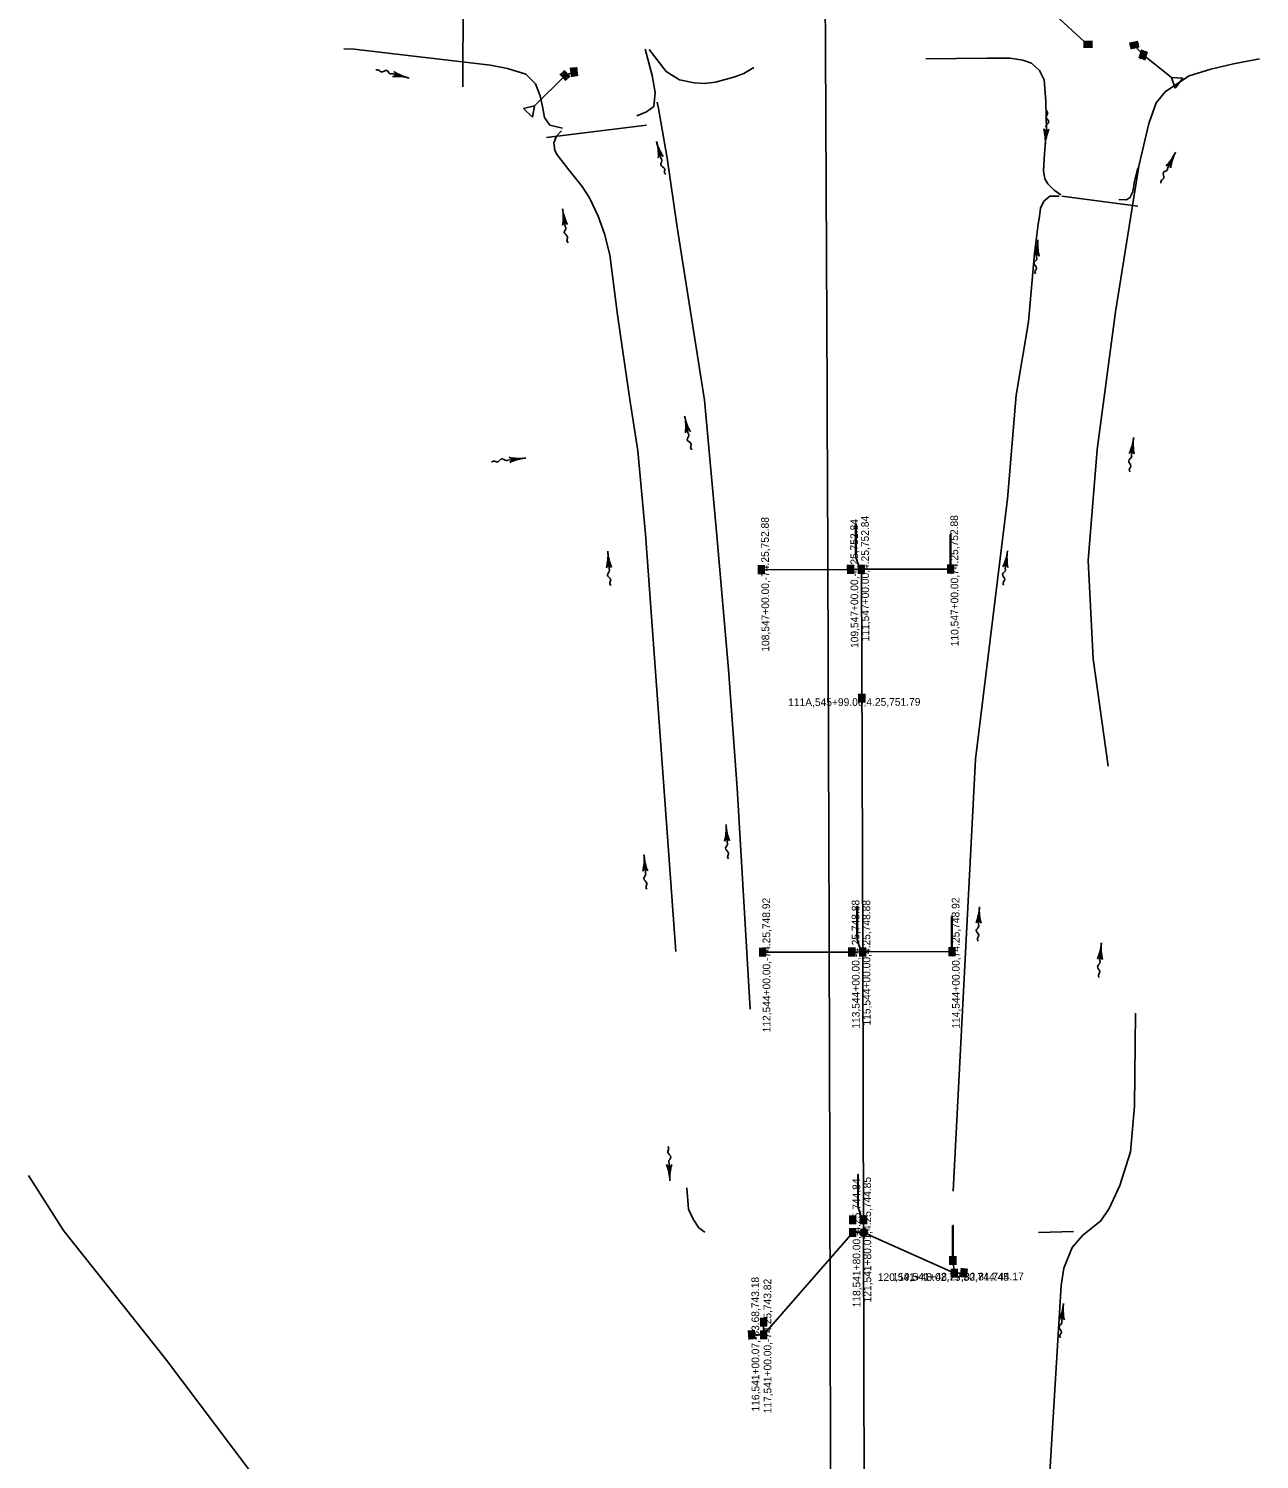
# Model space of a CAD drawing. Extents: x 593481 to 595859, y 101157 to 225994.
# Drawn here: x 593709 to 594675, y 153277 to 154399 of the extents above; entities that cross this region are included whole.
import ezdxf

# ---------------------------------------------------------------- set-up
doc = ezdxf.new("R2010")
doc.units = 0
for name, color, linetype in [('Default', 7, 'Continuous'), ('E_DTM_SpotElev', 7, 'Continuous'), ('E_PROF_GridMin', 7, 'Continuous'), ('Level 6', 7, 'Continuous'), ('P_DRN_SS_UG', 7, 'Continuous'), ('P_MAP_ContoursInter', 7, 'Continuous'), ('P_RDWY_C_and_G_H', 7, 'Continuous')]:
    doc.layers.add(name, color=color, linetype=linetype)

msp = doc.modelspace()

# ---------------------------------------------------------------- linework, layer by layer
at = {"layer": 'Default'}
msp.add_line((594334.5, 154382.7), (594308.8, 159385.6), dxfattribs=at)
msp.add_arc((250574.3, 152618.3), 343764.7, 0.103013, 0.29409, dxfattribs=at)
at = {"layer": 'E_DTM_SpotElev'}
for p, q in [((594008, 154360.4), (593994.3, 154363.9)), ((594506.8, 154307.6), (594507.7, 154321.7)), ((594201.9, 154310.7), (594205.6, 154297.1)), ((594608.9, 154302.3), (594602.8, 154289.6)), ((594128.3, 154257.9), (594130.4, 154244)), ((594501.1, 154233.7), (594499.9, 154219.7)), ((594224.1, 154095.3), (594226.8, 154081.5)), ((594576.1, 154078.6), (594574.4, 154064.6)), ((594099.4, 154062.5), (594085.3, 154060.9)), ((594163.8, 153989.4), (594164.8, 153975.3)), ((594477.1, 153989.6), (594475.4, 153975.6)), ((594256.5, 153775.1), (594257.3, 153761)), ((594192.2, 153751.4), (594193.2, 153737.3)), ((594455.2, 153710.7), (594454.5, 153696.6)), ((594550.8, 153682.3), (594549.7, 153668.2)), ((594212.5, 153495.8), (594211.8, 153509.9)), ((594521, 153399.7), (594519.7, 153385.7))]:
    msp.add_line(p, q, dxfattribs=at)
for points in [[(593995.1, 154361.6), (593998.7, 154362.7), (593996, 154365.5)], [(594505.6, 154320.5), (594507.4, 154317.2), (594509.6, 154320.3)], [(594207.2, 154298.9), (594204.4, 154301.5), (594203.3, 154297.9)], [(594605.2, 154289.9), (594604.8, 154293.7), (594601.6, 154291.7)], [(594132.2, 154245.6), (594129.7, 154248.4), (594128.2, 154245)], [(594502, 154220.8), (594500.3, 154224.2), (594498, 154221.1)], [(594228.5, 154083.2), (594225.9, 154085.9), (594224.6, 154082.4)], [(594086.9, 154059.1), (594089.8, 154061.4), (594086.4, 154063.1)], [(594576.5, 154065.7), (594575, 154069.1), (594572.6, 154066.1)], [(594166.7, 153976.8), (594164.4, 153979.8), (594162.7, 153976.5)], [(594477.6, 153976.7), (594476, 153980.1), (594473.6, 153977.2)], [(594259.2, 153762.5), (594257.1, 153765.6), (594255.2, 153762.2)], [(594195.1, 153738.8), (594192.8, 153741.8), (594191.1, 153738.5)], [(594456.5, 153697.9), (594454.7, 153701.2), (594452.6, 153698.1)], [(594551.8, 153669.3), (594550, 153672.7), (594547.8, 153669.7)], [(594209.9, 153508.5), (594212, 153505.4), (594213.9, 153508.7)], [(594521.8, 153386.8), (594520.1, 153390.2), (594517.8, 153387.2)]]:
    msp.add_lwpolyline(points, dxfattribs=at)
for centre, start, end in [((594018.2, 154401.1), 238.1531, 255.9155), ((593997.7, 154319.7), 75.9155, 93.6778), ((594464.9, 154310.2), 356.5125, 14.2748), ((594548.7, 154305.1), 158.7502, 176.5125), ((594242.4, 154321.7), 195.1541, 212.9164), ((594161.4, 154299.8), 357.3917, 15.1541), ((594571.2, 154320.6), 316.3732, 334.1356), ((594646.7, 154284), 154.1356, 171.8979), ((594086.8, 154251.8), 350.6256, 8.3879), ((594169.8, 154264), 188.3879, 206.1502), ((594459.2, 154237.1), 337.5935, 355.3558), ((594542.9, 154230.3), 175.3558, 193.1182), ((594265.2, 154103.5), 191.2545, 209.0168), ((594182.9, 154087.1), 353.4922, 11.2545), ((594534.5, 154083.7), 335.2209, 352.9833), ((594617.8, 154073.5), 172.9833, 190.7456), ((594094.6, 154104.2), 258.7469, 276.5092), ((594104.1, 154020.8), 96.5092, 114.2715), ((594121.9, 153986.4), 346.3551, 4.1174), ((594205.6, 153992.4), 184.1174, 201.8798), ((594435.5, 153994.8), 335.1954, 352.9578), ((594518.8, 153984.5), 172.9578, 190.7201), ((594214.6, 153772.7), 345.5959, 3.3582), ((594298.4, 153777.6), 183.3582, 201.1205), ((594150.3, 153748.4), 346.3551, 4.1174), ((594234, 153754.4), 184.1174, 201.8798), ((594413.3, 153712.9), 339.294, 357.0563), ((594497.1, 153708.6), 177.0563, 194.8186), ((594509, 153685.6), 337.6021, 355.3644), ((594592.6, 153678.9), 175.3644, 193.1267), ((594170.5, 153493.9), 2.5881, 20.3505), ((594254.4, 153497.7), 164.8258, 182.5881), ((594479.3, 153403.8), 336.6726, 354.435), ((594562.8, 153395.7), 174.435, 192.1973)]:
    msp.add_arc(centre, 42, start, end, dxfattribs=at)
for points in [[(593994.3, 154363.9), (593993.4, 154363.7), (593990.4, 154366.4), (593986, 154365.3), (593983.5, 154366.9), (593981.7, 154366.7)], [(594507.7, 154321.7), (594507.4, 154322.5), (594509.5, 154326), (594507.5, 154330.1), (594508.7, 154332.8), (594508.1, 154334.6)], [(594205.6, 154297.1), (594206.1, 154296.4), (594205.2, 154292.4), (594208.4, 154289.2), (594208.2, 154286.3), (594209.2, 154284.8)], [(594602.8, 154289.6), (594602.7, 154288.8), (594599.5, 154286.4), (594599.7, 154281.9), (594597.6, 154279.7), (594597.5, 154277.9)], [(594130.4, 154244), (594130.8, 154243.2), (594129.5, 154239.4), (594132.2, 154235.8), (594131.7, 154232.9), (594132.6, 154231.3)], [(594499.9, 154219.7), (594500.2, 154218.8), (594498, 154215.4), (594499.9, 154211.3), (594498.7, 154208.6), (594499.2, 154206.8)], [(594226.8, 154081.5), (594227.3, 154080.8), (594226.1, 154076.9), (594229.1, 154073.4), (594228.7, 154070.5), (594229.6, 154068.9)], [(594085.3, 154060.9), (594084.6, 154060.5), (594080.8, 154062), (594077.1, 154059.4), (594074.2, 154060), (594072.6, 154059.2)], [(594574.4, 154064.6), (594574.6, 154063.8), (594572.3, 154060.4), (594574, 154056.2), (594572.7, 154053.6), (594573.1, 154051.8)], [(594164.8, 153975.3), (594165.1, 153974.5), (594163.5, 153970.8), (594166, 153967), (594165.3, 153964.2), (594166, 153962.5)], [(594475.4, 153975.6), (594475.6, 153974.8), (594473.3, 153971.4), (594475, 153967.3), (594473.7, 153964.6), (594474.1, 153962.8)], [(594257.3, 153761), (594257.7, 153760.3), (594256, 153756.6), (594258.4, 153752.8), (594257.7, 153749.9), (594258.4, 153748.2)], [(594193.2, 153737.3), (594193.5, 153736.5), (594191.9, 153732.8), (594194.4, 153729.1), (594193.7, 153726.2), (594194.4, 153724.5)], [(594454.5, 153696.6), (594454.8, 153695.8), (594452.7, 153692.3), (594454.7, 153688.3), (594453.6, 153685.5), (594454.1, 153683.8)], [(594549.7, 153668.2), (594549.9, 153667.4), (594547.8, 153663.9), (594549.6, 153659.8), (594548.5, 153657.1), (594548.9, 153655.3)], [(594211.8, 153509.9), (594211.5, 153510.7), (594213.2, 153514.4), (594210.8, 153518.2), (594211.6, 153521.1), (594210.9, 153522.8)], [(594519.7, 153385.7), (594519.9, 153384.8), (594517.7, 153381.4), (594519.5, 153377.3), (594518.3, 153374.6), (594518.7, 153372.8)]]:
    msp.add_spline(points, degree=3, dxfattribs=at)
at = {"layer": 'E_PROF_GridMin'}
for p, q in [((594540.5, 154386.1), (594491.5, 154431.2)), ((594576.6, 154386.3), (594583.6, 154378.5)), ((594583.6, 154378.5), (594605.8, 154360.9)), ((594130.2, 154362.4), (594106.2, 154338.6)), ((594137.3, 154365.2), (594130.2, 154362.4)), ((594284.1, 153974.9), (594354.1, 153975.2)), ((594354.1, 153975.2), (594362.6, 153975.3)), ((594432.6, 153975.5), (594362.6, 153975.3)), ((594362.6, 153975.3), (594363.7, 153675.3)), ((594432.6, 153976.5), (594432.6, 153978.5)), ((594433.6, 153676.5), (594433.6, 153679)), ((594285.2, 153675), (594355.2, 153675.2)), ((594355.2, 153675.2), (594363.7, 153675.3)), ((594433.7, 153675.5), (594363.7, 153675.3)), ((594363.7, 153675.3), (594364.3, 153455.3)), ((594285.9, 153375.1), (594355.8, 153455.2)), ((594355.8, 153455.2), (594364.3, 153455.3)), ((594435.6, 153423.4), (594364.3, 153455.3)), ((594364.3, 153455.3), (594364.8, 153184.2)), ((594529, 153456), (594501.6, 153455.4)), ((594434.3, 153434.4), (594434.3, 153436.9)), ((594435.6, 153423.4), (594434.3, 153433.4)), ((594276.5, 153375.1), (594285.9, 153375.1)), ((594285.9, 153375.1), (594285.9, 153385.1))]:
    msp.add_line(p, q, dxfattribs=at)
for points in [[(594128.3, 154321.1), (594118.4, 154323.4), (594114.1, 154329.6), (594112.5, 154338.2), (594110.8, 154346.4), (594107, 154355.8), (594099.4, 154363.4), (594085.1, 154367.9), (594071.8, 154370.5), (593964.7, 154383.1), (593956.8, 154383.2)], [(594193.1, 154383.1), (594198.4, 154362.4), (594201, 154349.1), (594199.9, 154338.2), (594194, 154334), (594186.5, 154330.9)], [(594196.2, 154382.7), (594209.6, 154365.5), (594220, 154358.9), (594231.4, 154356.6), (594239.5, 154356.1), (594248.2, 154357.3), (594263.3, 154361.5), (594270.5, 154363.9), (594278.3, 154368.7)], [(594519, 154268.8), (594513.7, 154272.6), (594508.9, 154277.5), (594506.6, 154281.5), (594505.5, 154288), (594506.3, 154300.9), (594507.7, 154319.7), (594507.3, 154342), (594506, 154359), (594502.3, 154366.3), (594495.9, 154372.1), (594489.3, 154374.5), (594479.3, 154376), (594461.3, 154376), (594413.1, 154375.6)], [(594674.8, 154375.5), (594654.5, 154371.6), (594636.6, 154367.3), (594619.8, 154362.1), (594601.1, 154349.9), (594593.8, 154341), (594588.1, 154324.9), (594580.1, 154291.4), (594561.9, 154177), (594547.4, 154069.1), (594540.5, 153982.3), (594544.4, 153905.1), (594556.2, 153820.9)], [(594202.5, 154341.4), (594203.4, 154336.5), (594210.2, 154297.7), (594218.2, 154243.4), (594239.5, 154107.8), (594249.3, 154001.8), (594258.4, 153896.6), (594265.3, 153803.8), (594275.5, 153630.4)], [(594127.3, 154319), (594123.6, 154314.8), (594121.4, 154309.7), (594122.3, 154303.6), (594124, 154300.2), (594133.1, 154288.5), (594143.6, 154275.3), (594149.5, 154266.4), (594156.2, 154252.1), (594161.2, 154238.3), (594165.2, 154221.7), (594171.3, 154174.7), (594181.1, 154108.4), (594187.2, 154068.1), (594193.4, 154002.9), (594217.2, 153675.5)], [(594579.4, 154290), (594576.9, 154279.6), (594575.4, 154271.3), (594573.1, 154266.5), (594570.2, 154264.9), (594564.5, 154265.3)], [(594517.6, 154267.7), (594510.4, 154267.7), (594507.4, 154265.3), (594505.7, 154263.8), (594503.2, 154258.4), (594502.3, 154251.9), (594501.3, 154245.8), (594498.5, 154222.8), (594493.6, 154169.3), (594483.9, 154111.8), (594477.3, 154030.5), (594452.1, 153826.4), (594434.7, 153487.6)], [(594361.2, 153976.3), (594358.3, 153984.8), (594358.3, 153986.8)], [(594362.3, 153676.3), (594359.4, 153684.8), (594359.4, 153686.8)], [(594577.5, 153627.4), (594576.8, 153554.4), (594573.6, 153518.6), (594565.2, 153492.1), (594557, 153474.1), (594550.3, 153464.5), (594536.3, 153453.1), (594527.8, 153443.5), (594521.5, 153427.4), (594519.3, 153413.7), (594507, 153211.5), (594503.1, 153118.7), (594500.3, 153076.8)], [(594231.3, 152595.8), (594238, 152608), (594241.5, 152629.1), (594238.7, 152654.6), (594233.1, 152686.7), (594216.9, 152735.1), (594189.3, 152811.5), (594166.9, 152857.5), (594145.5, 152897.2), (593987.3, 153130.1), (593816.8, 153356.3), (593736.8, 153457), (593709.5, 153500.1)], [(594239.9, 153455.5), (594235.1, 153459), (594230.6, 153465.7), (594227.1, 153473.5), (594225.7, 153490.3)], [(594362.9, 153466.3), (594360, 153474.8), (594360, 153476.8)]]:
    msp.add_lwpolyline(points, dxfattribs=at)
msp.add_arc((595235.5, -190446.6), 343870.9, 90.131684, 90.133649, dxfattribs=at)
at = {"layer": 'P_DRN_SS_UG'}
for p, q in [((594543.8, 154389.2), (594536.9, 154389.1)), ((594543.8, 154388.3), (594536.9, 154388.2)), ((594543.8, 154387.4), (594536.9, 154387.3)), ((594543.8, 154386.5), (594536.9, 154386.4)), ((594543.8, 154385.6), (594536.9, 154385.5)), ((594543.8, 154384.7), (594536.9, 154384.6)), ((594579.5, 154389.2), (594572.8, 154387.7)), ((594579.7, 154388.3), (594573, 154386.8)), ((594579.9, 154387.5), (594573.2, 154386)), ((594580.1, 154386.6), (594573.4, 154385.1)), ((594580.3, 154385.7), (594573.6, 154384.2)), ((594580.5, 154384.8), (594573.8, 154383.3)), ((594582.5, 154382.5), (594580.4, 154375.9)), ((594583.4, 154382.2), (594581.3, 154375.6)), ((594584.2, 154381.9), (594582.1, 154375.4)), ((594585.1, 154381.6), (594583, 154375.1)), ((594585.9, 154381.4), (594583.9, 154374.8)), ((594586.8, 154381.1), (594584.7, 154374.5)), ((594130.9, 154358.4), (594126.2, 154363.4)), ((594131.6, 154359), (594126.9, 154364)), ((594132.2, 154359.6), (594127.5, 154364.6)), ((594132.9, 154360.2), (594128.2, 154365.2)), ((594133.5, 154360.8), (594128.8, 154365.8)), ((594134.2, 154361.4), (594129.5, 154366.4)), ((594135.5, 154361.5), (594134.6, 154368.4)), ((594136.4, 154361.6), (594135.5, 154368.5)), ((594137.3, 154361.7), (594136.4, 154368.6)), ((594138.1, 154361.9), (594137.3, 154368.7)), ((594139, 154362), (594138.2, 154368.8)), ((594139.9, 154362.1), (594139.1, 154368.9)), ((594281.9, 153971.5), (594281.8, 153978.4)), ((594282.8, 153971.5), (594282.7, 153978.4)), ((594283.7, 153971.5), (594283.6, 153978.4)), ((594284.6, 153971.5), (594284.5, 153978.4)), ((594285.5, 153971.5), (594285.4, 153978.4)), ((594286.4, 153971.5), (594286.3, 153978.4)), ((594351.9, 153971.8), (594351.8, 153978.7)), ((594352.8, 153971.8), (594352.7, 153978.7)), ((594353.7, 153971.8), (594353.6, 153978.7)), ((594354.6, 153971.8), (594354.5, 153978.7)), ((594355.5, 153971.8), (594355.4, 153978.7)), ((594356.4, 153971.8), (594356.3, 153978.7)), ((594360.4, 153971.8), (594360.3, 153978.7)), ((594361.3, 153971.8), (594361.2, 153978.7)), ((594362.2, 153971.8), (594362.1, 153978.7)), ((594363.1, 153971.8), (594363, 153978.7)), ((594364, 153971.8), (594363.9, 153978.7)), ((594364.9, 153971.8), (594364.8, 153978.7)), ((594430.4, 153972.1), (594430.3, 153979)), ((594431.3, 153972.1), (594431.2, 153979)), ((594432.2, 153972.1), (594432.1, 153979)), ((594433.1, 153972.1), (594433, 153979)), ((594434, 153972.1), (594433.9, 153979)), ((594434.9, 153972.1), (594434.8, 153979)), ((594360.7, 153870.8), (594360.7, 153877.7)), ((594361.6, 153870.8), (594361.6, 153877.7)), ((594362.5, 153870.8), (594362.5, 153877.7)), ((594363.4, 153870.8), (594363.4, 153877.7)), ((594364.3, 153870.8), (594364.3, 153877.7)), ((594365.2, 153870.8), (594365.2, 153877.7)), ((594282.9, 153671.6), (594282.9, 153678.4)), ((594283.8, 153671.6), (594283.8, 153678.4)), ((594284.7, 153671.6), (594284.7, 153678.4)), ((594285.6, 153671.6), (594285.6, 153678.5)), ((594286.5, 153671.6), (594286.5, 153678.5)), ((594287.4, 153671.6), (594287.4, 153678.5)), ((594352.9, 153671.8), (594352.9, 153678.7)), ((594353.8, 153671.8), (594353.8, 153678.7)), ((594354.7, 153671.8), (594354.7, 153678.7)), ((594355.6, 153671.8), (594355.6, 153678.7)), ((594356.5, 153671.8), (594356.5, 153678.7)), ((594357.4, 153671.8), (594357.4, 153678.7)), ((594361.4, 153671.8), (594361.4, 153678.7)), ((594362.3, 153671.8), (594362.3, 153678.7)), ((594363.2, 153671.8), (594363.2, 153678.7)), ((594364.1, 153671.8), (594364.1, 153678.7)), ((594365, 153671.8), (594365, 153678.7)), ((594365.9, 153671.8), (594365.9, 153678.7)), ((594431.4, 153672), (594431.4, 153678.9)), ((594432.3, 153672), (594432.3, 153678.9)), ((594433.2, 153672), (594433.2, 153678.9)), ((594434.1, 153672), (594434.1, 153678.9)), ((594435, 153672), (594435, 153678.9)), ((594435.9, 153672), (594435.9, 153678.9)), ((594353.5, 153461.8), (594353.5, 153468.7)), ((594354.4, 153461.8), (594354.4, 153468.7)), ((594355.3, 153461.8), (594355.3, 153468.7)), ((594356.2, 153461.8), (594356.2, 153468.7)), ((594357.1, 153461.8), (594357.1, 153468.7)), ((594358, 153461.8), (594358, 153468.7)), ((594362, 153461.8), (594362, 153468.7)), ((594362.9, 153461.8), (594362.9, 153468.7)), ((594363.8, 153461.8), (594363.8, 153468.7)), ((594364.7, 153461.8), (594364.7, 153468.7)), ((594365.6, 153461.8), (594365.6, 153468.7)), ((594366.5, 153461.8), (594366.5, 153468.7)), ((594353.5, 153451.8), (594353.5, 153458.7)), ((594354.4, 153451.8), (594354.4, 153458.7)), ((594355.3, 153451.8), (594355.3, 153458.7)), ((594356.2, 153451.8), (594356.2, 153458.7)), ((594357.1, 153451.8), (594357.1, 153458.7)), ((594358, 153451.8), (594358, 153458.7)), ((594432.1, 153429.9), (594432.1, 153436.8)), ((594433, 153429.9), (594433, 153436.8)), ((594433.9, 153429.9), (594433.9, 153436.8)), ((594434.8, 153429.9), (594434.8, 153436.8)), ((594435.7, 153429.9), (594435.7, 153436.8)), ((594436.6, 153430), (594436.6, 153436.8)), ((594433.3, 153420), (594433.3, 153426.9)), ((594434.2, 153420), (594434.2, 153426.9)), ((594435.1, 153420), (594435.1, 153426.9)), ((594436, 153420), (594436, 153426.9)), ((594436.9, 153420), (594436.9, 153426.9)), ((594437.8, 153420), (594437.8, 153426.9)), ((594440.3, 153420.5), (594441, 153427.4)), ((594441.2, 153420.4), (594441.9, 153427.3)), ((594442.1, 153420.3), (594442.8, 153427.2)), ((594443, 153420.2), (594443.7, 153427.1)), ((594443.9, 153420.1), (594444.6, 153427)), ((594444.8, 153420), (594445.5, 153426.9)), ((594283.7, 153381.7), (594283.7, 153388.5)), ((594284.6, 153381.7), (594284.6, 153388.5)), ((594285.5, 153381.7), (594285.5, 153388.5)), ((594286.4, 153381.7), (594286.4, 153388.5)), ((594287.3, 153381.7), (594287.3, 153388.5)), ((594288.2, 153381.7), (594288.2, 153388.5)), ((594274.5, 153371.5), (594274, 153378.4)), ((594275.4, 153371.6), (594274.9, 153378.5)), ((594276.3, 153371.7), (594275.8, 153378.5)), ((594277.2, 153371.7), (594276.7, 153378.6)), ((594278.1, 153371.8), (594277.6, 153378.6)), ((594279, 153371.9), (594278.5, 153378.7)), ((594283.7, 153371.6), (594283.7, 153378.5)), ((594284.6, 153371.6), (594284.6, 153378.5)), ((594285.5, 153371.6), (594285.5, 153378.5)), ((594286.4, 153371.6), (594286.4, 153378.5)), ((594287.3, 153371.6), (594287.3, 153378.5)), ((594288.2, 153371.6), (594288.2, 153378.5))]:
    msp.add_line(p, q, dxfattribs=at)
for points in [[(594541.3, 154387.9), (594539.3, 154387.9), (594539.3, 154385.9), (594541.3, 154385.9)], [(594577.4, 154387.5), (594575.4, 154387), (594575.9, 154385.1), (594577.8, 154385.5)], [(594583, 154379.8), (594582.4, 154377.9), (594584.3, 154377.2), (594584.9, 154379.2)], [(594131.6, 154362.4), (594130.2, 154363.8), (594128.8, 154362.4), (594130.1, 154361)], [(594138.4, 154364.3), (594138.2, 154366.3), (594136.2, 154366.1), (594136.4, 154364.1)], [(594358, 154010.8), (594358.4, 154010.8), (594358.5, 153986.8), (594358.1, 153986.8)], [(594432.3, 154002.5), (594432.7, 154002.5), (594432.8, 153978.5), (594432.3, 153978.5)], [(594285.1, 153973.9), (594285.1, 153975.9), (594283.1, 153975.9), (594283.1, 153973.9)], [(594355.1, 153974.2), (594355.1, 153976.2), (594353.1, 153976.2), (594353.1, 153974.2)], [(594363.6, 153974.3), (594363.6, 153976.3), (594361.6, 153976.3), (594361.6, 153974.3)], [(594433.6, 153974.5), (594433.6, 153976.5), (594431.6, 153976.5), (594431.6, 153974.5)], [(594364, 153873.3), (594364, 153875.3), (594362, 153875.3), (594362, 153873.3)], [(594359.1, 153710.8), (594359.5, 153710.8), (594359.6, 153686.8), (594359.1, 153686.8)], [(594433.3, 153703), (594433.8, 153703), (594433.9, 153679), (594433.4, 153679)], [(594286.2, 153674), (594286.1, 153676), (594284.1, 153676), (594284.2, 153674)], [(594356.2, 153674.2), (594356.1, 153676.2), (594354.1, 153676.2), (594354.2, 153674.2)], [(594364.7, 153674.3), (594364.6, 153676.3), (594362.6, 153676.3), (594362.7, 153674.3)], [(594434.7, 153674.5), (594434.6, 153676.5), (594432.6, 153676.5), (594432.7, 153674.5)], [(594359.7, 153500.8), (594360.1, 153500.8), (594360.2, 153476.8), (594359.7, 153476.8)], [(594356.7, 153464.2), (594356.7, 153466.2), (594354.7, 153466.2), (594354.7, 153464.2)], [(594365.3, 153464.3), (594365.3, 153466.3), (594363.3, 153466.3), (594363.3, 153464.3)], [(594356.8, 153454.2), (594356.8, 153456.2), (594354.8, 153456.2), (594354.8, 153454.2)], [(594434, 153460.9), (594434.5, 153460.9), (594434.5, 153436.9), (594434.1, 153436.9)], [(594435.3, 153432.4), (594435.3, 153434.4), (594433.3, 153434.4), (594433.3, 153432.4)], [(594436.6, 153422.4), (594436.6, 153424.4), (594434.6, 153424.4), (594434.6, 153422.4)], [(594443.8, 153422.6), (594444, 153424.6), (594442, 153424.8), (594441.8, 153422.8)], [(594277.6, 153374.2), (594277.4, 153376.2), (594275.4, 153376.1), (594275.6, 153374.1)], [(594286.9, 153384.1), (594286.9, 153386.1), (594284.9, 153386.1), (594284.9, 153384.1)], [(594286.9, 153374.1), (594286.9, 153376.1), (594284.9, 153376.1), (594284.9, 153374.1)]]:
    msp.add_lwpolyline(points, close=True, dxfattribs=at)
at = {"layer": 'P_MAP_ContoursInter'}
for p, q in [((594050.1, 154353.5), (594050.6, 154501.4)), ((594115.7, 154313.7), (594194.2, 154323.4)), ((594519.8, 154267.9), (594579.3, 154260))]:
    msp.add_line(p, q, dxfattribs=at)
for radius in [2.98, 2.4, 1.8, 1.2, 0.6]:
    msp.add_circle((594364.3, 153455.3), radius, dxfattribs=at)
at = {"layer": 'P_RDWY_C_and_G_H'}
for p, q in [((594614.8, 154360.3), (594605.8, 154360.9)), ((594605.8, 154360.9), (594608.7, 154352.4)), ((594614.8, 154360.3), (594608.7, 154352.4)), ((594106.2, 154338.6), (594097.5, 154336.5)), ((594104.8, 154329.7), (594097.5, 154336.5)), ((594104.8, 154329.7), (594106.2, 154338.6))]:
    msp.add_line(p, q, dxfattribs=at)

# ---------------------------------------------------------------- texts
at = {"layer": 'Level 6'}
for s, rotation, p in [('108,547+00.00,-74.25,752.88', 90.2262, (594290.4, 153910.7)), ('109,547+00.00,-4.25,752.84', 90.2262, (594360.3, 153913.6)), ('111,547+00.00,4.25,752.84', 90.2262, (594368.8, 153918.8)), ('110,547+00.00,74.25,752.88', 90.2262, (594438.8, 153914.9)), ('111A,545+99.00,4.25,751.79', 0.2093, (594305.2, 153868)), ('112,544+00.00,-74.25,748.92', 90.1762, (594291.3, 153612.2)), ('113,544+00.00,-4.25,748.88', 90.1762, (594361.3, 153615.1)), ('115,544+00.00,4.25,748.88', 90.1762, (594369.8, 153617.6)), ('114,544+00.00,74.25,748.92', 90.1762, (594439.8, 153615.1)), ('121,541+80.01,4.25,744.85', 90.1395, (594370.4, 153400.5)), ('118,541+80.00,-4.25,744.84', 90.1395, (594361.9, 153396.6)), ('116,541+00.07,-83.68,743.18', 90.1262, (594282.6, 153315)), ('120,541+48.02,75.50,744.45', 0.1342, (594375.5, 153417.3)), ('119,541+48.27,82.81,744.17', 0.1342, (594387.1, 153417.6)), ('117,541+00.00,-74.25,743.82', 90.1262, (594292.1, 153313.5))]:
    msp.add_text(s, height=6, rotation=rotation, dxfattribs=at).set_placement(p)

doc.saveas('drawing.dxf')
